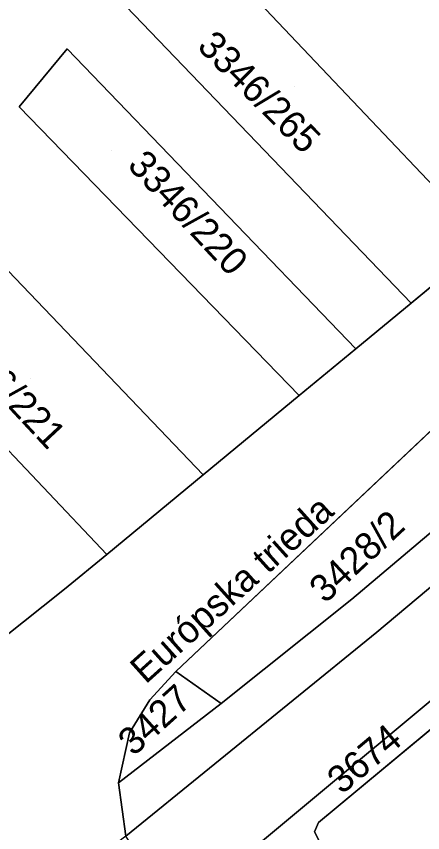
# Model space of a CAD drawing. Extents: x -262715 to -259381, y -1237238 to -1231182.
# Drawn here: x -261952.7 to -261922.9, y -1235609.2 to -1235549.4 of the extents above; entities that cross this region are included whole.
import ezdxf

# ---------------------------------------------------------------- set-up
doc = ezdxf.new("R2010")
doc.units = 0
for name, color, linetype in [('body_kn', 7, 'Continuous'), ('kladpar_druhypozemkov', 7, 'Continuous'), ('kladpar_hranice', 7, 'Continuous'), ('kladpar_parcelnecisla', 7, 'Continuous'), ('kladpar_plochy', 7, 'Continuous'), ('popisy', 7, 'Continuous')]:
    doc.layers.add(name, color=color, linetype=linetype)

msp = doc.modelspace()

# ---------------------------------------------------------------- linework, layer by layer
at = {"layer": 'body_kn'}
for p, q in [((-261948.93, -1235551.8), (-261948.93, -1235551.8)), ((-261952.45, -1235556.04), (-261952.45, -1235556.04)), ((-261952.45, -1235556.04), (-261952.45, -1235556.04)), ((-261923.72, -1235570.4), (-261923.72, -1235570.4)), ((-261923.72, -1235570.4), (-261923.72, -1235570.4)), ((-261927.77, -1235573.74), (-261927.77, -1235573.74)), ((-261927.77, -1235573.74), (-261927.77, -1235573.74)), ((-261931.92, -1235577.16), (-261931.92, -1235577.16)), ((-261931.92, -1235577.16), (-261931.92, -1235577.16)), ((-261938.97, -1235582.97), (-261938.97, -1235582.97)), ((-261938.97, -1235582.97), (-261938.97, -1235582.97)), ((-261946.02, -1235588.79), (-261946.02, -1235588.79)), ((-261946.02, -1235588.79), (-261946.02, -1235588.79)), ((-261949.12, -1235591.34), (-261949.12, -1235591.34)), ((-261928.07, -1235592.06), (-261928.07, -1235592.06)), ((-261926.23, -1235594.49), (-261926.23, -1235594.49)), ((-261940.96, -1235597.37), (-261940.96, -1235597.37)), ((-261940.96, -1235597.37), (-261940.96, -1235597.37)), ((-261942.88, -1235599.43), (-261942.88, -1235599.43)), ((-261937.65, -1235599.71), (-261937.65, -1235599.71)), ((-261944.35, -1235601.85), (-261944.35, -1235601.85)), ((-261945.16, -1235605.52), (-261945.16, -1235605.52)), ((-261930.5, -1235608.41), (-261930.5, -1235608.41)), ((-261930.8, -1235609.1), (-261930.8, -1235609.1))]:
    msp.add_line(p, q, dxfattribs=at)
at = {"layer": 'kladpar_druhypozemkov'}
for p, q in [((-261932.25, -1235554.52), (-261932.25, -1235554.52)), ((-261945.69, -1235559.23), (-261945.69, -1235559.23)), ((-261951.65, -1235575.94), (-261951.65, -1235575.94)), ((-261927.62, -1235587.74), (-261927.62, -1235587.74)), ((-261941.22, -1235598.99), (-261941.22, -1235598.99)), ((-261922.95, -1235601.85), (-261922.95, -1235601.85))]:
    msp.add_line(p, q, dxfattribs=at)
at = {"layer": 'kladpar_hranice'}
for p, q in [((-261923.72, -1235570.4), (-261927.77, -1235573.74)), ((-261931.92, -1235577.16), (-261927.77, -1235573.74)), ((-261931.92, -1235577.16), (-261938.97, -1235582.97)), ((-261938.97, -1235582.97), (-261931.92, -1235577.16)), ((-261946.02, -1235588.79), (-261938.97, -1235582.97))]:
    msp.add_line(p, q, dxfattribs=at)
for points in [[(-261846.13, -1235482.73), (-261858.58, -1235505.25), (-261866.27, -1235518.41), (-261868.02, -1235522.25), (-261868.52, -1235525.08), (-261868.52, -1235528.61), (-261868.2, -1235531.36), (-261866.87, -1235534.93), (-261872.16, -1235542.06), (-261875.04, -1235540.58), (-261878.9, -1235540.24), (-261881.69, -1235540.95), (-261884.4, -1235542.27), (-261886.67, -1235544.07), (-261901.92, -1235560.42), (-261915.13, -1235573), (-261940.96, -1235597.37), (-261942.88, -1235599.43), (-261944.35, -1235601.85), (-261945.16, -1235605.52), (-261944.62, -1235609.41), (-261950.01, -1235613.48), (-261952.22, -1235611.84), (-261953.84, -1235611.35)], [(-261927.77, -1235573.74), (-261923.72, -1235570.4), (-261920.41, -1235567.67), (-261918.41, -1235565.69), (-261900.02, -1235547.45), (-261898.39, -1235545.84), (-261895.71, -1235542.69), (-261892.46, -1235538.87)], [(-261873.17, -1235544.4), (-261874.01, -1235544.25), (-261889.55, -1235561.11), (-261892.81, -1235564.51), (-261908.64, -1235579.75), (-261926.23, -1235594.49), (-261944.62, -1235609.41), (-261945.16, -1235605.52), (-261937.65, -1235599.71), (-261928.07, -1235592.06), (-261910.51, -1235577.27), (-261891.39, -1235558.61), (-261875.04, -1235540.58), (-261872.16, -1235542.06)], [(-261918.41, -1235565.69), (-261941.24, -1235541.67), (-261945.79, -1235547.43), (-261923.72, -1235570.4)], [(-261923.72, -1235570.4), (-261945.79, -1235547.43), (-261941.24, -1235541.67), (-261918.41, -1235565.69)], [(-261927.77, -1235573.74), (-261948.93, -1235551.8), (-261952.45, -1235556.04), (-261931.92, -1235577.16)], [(-261952.45, -1235556.04), (-261948.93, -1235551.8), (-261927.77, -1235573.74), (-261931.92, -1235577.16), (-261952.45, -1235556.04)], [(-261901.92, -1235560.42), (-261891.39, -1235558.61), (-261910.51, -1235577.27), (-261928.07, -1235592.06), (-261937.65, -1235599.71), (-261940.96, -1235597.37), (-261915.13, -1235573), (-261901.92, -1235560.42)], [(-261938.97, -1235582.97), (-261958.58, -1235562.51), (-261964.7, -1235569.1), (-261946.02, -1235588.79)], [(-261964.7, -1235569.1), (-261958.58, -1235562.51), (-261938.97, -1235582.97), (-261946.02, -1235588.79), (-261964.7, -1235569.1)], [(-261892.81, -1235564.51), (-261891.96, -1235564.42), (-261891.16, -1235564.74), (-261888.29, -1235569.39), (-261888.16, -1235569.99), (-261888.7, -1235570.92), (-261913.09, -1235591.16), (-261917.78, -1235595.76), (-261934.77, -1235609.88), (-261940.96, -1235614.79), (-261944.62, -1235609.41), (-261926.23, -1235594.49), (-261908.64, -1235579.75), (-261892.81, -1235564.51)], [(-261918.41, -1235565.69), (-261920.41, -1235567.67), (-261923.72, -1235570.4)], [(-261888.29, -1235569.39), (-261886.19, -1235573.47), (-261887.55, -1235572.9), (-261888.73, -1235572.92), (-261894.81, -1235578.24), (-261898.55, -1235581.07), (-261908.45, -1235589.32), (-261912, -1235592.28), (-261916.81, -1235597.09), (-261920.97, -1235600.5), (-261930.5, -1235608.41), (-261930.8, -1235609.1), (-261930.46, -1235609.76), (-261932.98, -1235612.06), (-261939.09, -1235616.96), (-261940.96, -1235614.79), (-261934.77, -1235609.88), (-261917.78, -1235595.76), (-261913.09, -1235591.16), (-261888.7, -1235570.92), (-261888.16, -1235569.99), (-261888.29, -1235569.39)], [(-261939.09, -1235616.96), (-261932.98, -1235612.06), (-261930.46, -1235609.76), (-261930.8, -1235609.1), (-261930.5, -1235608.41), (-261920.97, -1235600.5), (-261916.81, -1235597.09), (-261912, -1235592.28), (-261908.45, -1235589.32), (-261898.55, -1235581.07), (-261894.81, -1235578.24), (-261888.73, -1235572.92), (-261887.55, -1235572.9), (-261886.19, -1235573.47)], [(-261946.02, -1235588.79), (-261949.12, -1235591.34), (-261953.69, -1235594.96)], [(-261953.69, -1235594.96), (-261949.12, -1235591.34), (-261946.02, -1235588.79)], [(-261940.96, -1235597.37), (-261937.65, -1235599.71), (-261945.16, -1235605.52), (-261944.35, -1235601.85), (-261942.88, -1235599.43), (-261940.96, -1235597.37)]]:
    msp.add_lwpolyline(points, dxfattribs=at)
at = {"layer": 'kladpar_plochy'}
for p, q in [((-261923.72, -1235570.4), (-261920.41, -1235567.67)), ((-261927.77, -1235573.74), (-261923.72, -1235570.4)), ((-261915.13, -1235573), (-261940.96, -1235597.37)), ((-261931.92, -1235577.16), (-261927.77, -1235573.74)), ((-261938.97, -1235582.97), (-261931.92, -1235577.16)), ((-261946.02, -1235588.79), (-261938.97, -1235582.97)), ((-261949.12, -1235591.34), (-261946.02, -1235588.79)), ((-261953.69, -1235594.96), (-261949.12, -1235591.34)), ((-261940.96, -1235597.37), (-261942.88, -1235599.43)), ((-261942.88, -1235599.43), (-261944.35, -1235601.85)), ((-261930.5, -1235608.41), (-261920.97, -1235600.5)), ((-261944.35, -1235601.85), (-261945.16, -1235605.52)), ((-261945.16, -1235605.52), (-261944.62, -1235609.41)), ((-261930.8, -1235609.1), (-261930.5, -1235608.41)), ((-261930.46, -1235609.76), (-261930.8, -1235609.1))]:
    msp.add_line(p, q, dxfattribs=at)
for points in [[(-261865.96, -1235502.06), (-261876.49, -1235518.47), (-261877.31, -1235519.57), (-261884.23, -1235512.28), (-261901.19, -1235491.33), (-261904.18, -1235508.07), (-261915.61, -1235514.6), (-261892.46, -1235538.87), (-261895.71, -1235542.69), (-261920.11, -1235517.18), (-261925.29, -1235521.08), (-261900.02, -1235547.45), (-261918.41, -1235565.69), (-261941.24, -1235541.67), (-261945.79, -1235547.43), (-261923.72, -1235570.4), (-261927.77, -1235573.74), (-261948.93, -1235551.8), (-261952.45, -1235556.04), (-261931.92, -1235577.16), (-261938.97, -1235582.97), (-261958.58, -1235562.51)], [(-261873.17, -1235544.4), (-261874.01, -1235544.25), (-261889.55, -1235561.11), (-261892.81, -1235564.51), (-261908.64, -1235579.75), (-261926.23, -1235594.49), (-261944.62, -1235609.41), (-261945.16, -1235605.52), (-261937.65, -1235599.71), (-261928.07, -1235592.06), (-261910.51, -1235577.27), (-261891.39, -1235558.61), (-261875.04, -1235540.58), (-261872.16, -1235542.06)], [(-261964.7, -1235569.1), (-261946.02, -1235588.79), (-261949.12, -1235591.34), (-261953.69, -1235594.96)]]:
    msp.add_lwpolyline(points, dxfattribs=at)
for points in [[(-261923.72, -1235570.4), (-261945.79, -1235547.43), (-261941.24, -1235541.67), (-261918.41, -1235565.69), (-261920.41, -1235567.67)], [(-261952.45, -1235556.04), (-261948.93, -1235551.8), (-261927.77, -1235573.74), (-261931.92, -1235577.16)], [(-261901.92, -1235560.42), (-261891.39, -1235558.61), (-261910.51, -1235577.27), (-261928.07, -1235592.06), (-261937.65, -1235599.71), (-261940.96, -1235597.37), (-261915.13, -1235573)], [(-261964.7, -1235569.1), (-261958.58, -1235562.51), (-261938.97, -1235582.97), (-261946.02, -1235588.79)], [(-261892.81, -1235564.51), (-261891.96, -1235564.42), (-261891.16, -1235564.74), (-261888.29, -1235569.39), (-261888.16, -1235569.99), (-261888.7, -1235570.92), (-261913.09, -1235591.16), (-261917.78, -1235595.76), (-261934.77, -1235609.88), (-261940.96, -1235614.79), (-261944.62, -1235609.41), (-261926.23, -1235594.49), (-261908.64, -1235579.75)], [(-261888.29, -1235569.39), (-261886.19, -1235573.47), (-261887.55, -1235572.9), (-261888.73, -1235572.92), (-261894.81, -1235578.24), (-261898.55, -1235581.07), (-261908.45, -1235589.32), (-261912, -1235592.28), (-261916.81, -1235597.09), (-261920.97, -1235600.5), (-261930.5, -1235608.41), (-261930.8, -1235609.1), (-261930.46, -1235609.76), (-261932.98, -1235612.06), (-261939.09, -1235616.96), (-261940.96, -1235614.79), (-261934.77, -1235609.88), (-261917.78, -1235595.76), (-261913.09, -1235591.16), (-261888.7, -1235570.92), (-261888.16, -1235569.99)], [(-261940.96, -1235597.37), (-261937.65, -1235599.71), (-261945.16, -1235605.52), (-261944.35, -1235601.85), (-261942.88, -1235599.43)]]:
    msp.add_lwpolyline(points, close=True, dxfattribs=at)

# ---------------------------------------------------------------- texts
at = {"layer": 'kladpar_parcelnecisla'}
for s, rotation, p in [('3346/265', 315, (-261939.478, -1235551.706)), ('3346/220', 313, (-261944.584, -1235560.379)), ('3346/221', 313, (-261957.924, -1235573.062)), ('3428/2', 43, (-261930.02, -1235592.448)), ('3427', 42, (-261944.067, -1235603.619)), ('3674', 40, (-261928.802, -1235606.41))]:
    msp.add_text(s, height=2, rotation=rotation, dxfattribs=at).set_placement(p)
at = {"layer": 'popisy'}
msp.add_text('Európska trieda', height=2, rotation=42, dxfattribs=at).set_placement((-261943.175, -1235598.334))

doc.saveas('drawing.dxf')
